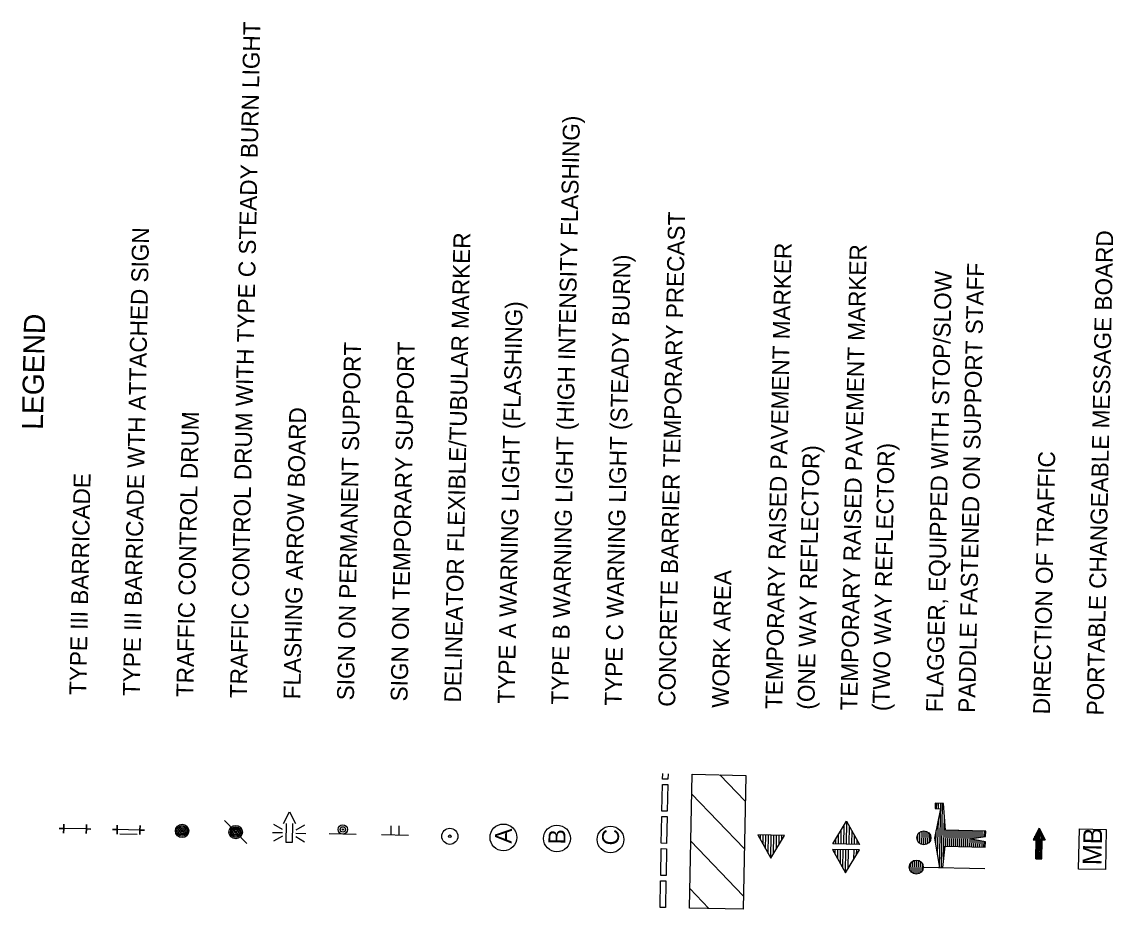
# Model space of a CAD drawing. Extents: x 327762 to 372975, y 127949 to 220470.
# Drawn here: x 327762 to 339988, y 174328 to 184269 of the extents above; entities that cross this region are included whole.
import ezdxf

# ---------------------------------------------------------------- set-up
doc = ezdxf.new("R2010")
doc.units = 0
for name, color, linetype in [('GSOUTLINE', 7, 'Continuous'), ('Level 31', 7, 'Continuous'), ('P_RDWY_Text', 7, 'Continuous'), ('P_TC', 7, 'Continuous')]:
    doc.layers.add(name, color=color, linetype=linetype)

msp = doc.modelspace()

# ---------------------------------------------------------------- linework, layer by layer
at = {"layer": 'GSOUTLINE'}
msp.add_lwpolyline([(335002, 175845), (335001, 175785), (334941, 175786), (334942, 175846)], dxfattribs=at)
for points in [[(334933, 175426), (334939, 175726), (334999, 175725), (334993, 175425)], [(334926, 175066), (334932, 175366), (334992, 175365), (334986, 175065)], [(334919, 174706), (334925, 175006), (334985, 175005), (334979, 174705)], [(334912, 174347), (334918, 174646), (334978, 174645), (334972, 174345)]]:
    msp.add_lwpolyline(points, close=True, dxfattribs=at)
at = {"layer": 'P_RDWY_Text'}
for p, q in [((339160, 175236), (339091, 175106)), ((339148, 174891), (339154, 175225)), ((339160, 175236), (339226, 175103)), ((339161, 174891), (339168, 175221)), ((339091, 175106), (339226, 175103)), ((339098, 175106), (339098, 175119)), ((339111, 175106), (339112, 175145)), ((339121, 174891), (339125, 175105)), ((339125, 175106), (339126, 175172)), ((339134, 174891), (339140, 175198)), ((339175, 174890), (339181, 175195)), ((339188, 174890), (339192, 175104)), ((339192, 175104), (339194, 175169)), ((339206, 175104), (339207, 175142)), ((339219, 175104), (339220, 175116)), ((339121, 174891), (339188, 174890)), ((339154, 174891), (339154, 174891))]:
    msp.add_line(p, q, dxfattribs=at)
at = {"layer": 'P_TC'}
for p, q in [((335867, 175537), (335582, 175833)), ((335856, 175006), (335266, 175620)), ((338054, 175453), (337988, 175125)), ((337996, 175515), (337994, 175455)), ((337994, 175455), (338054, 175453)), ((338088, 175513), (337996, 175515)), ((338010, 175454), (338011, 175514)), ((338032, 175454), (338033, 175514)), ((338041, 174793), (338056, 175513)), ((338064, 174793), (338078, 175513)), ((338110, 175212), (338088, 175513)), ((330692, 175289), (330761, 175419)), ((330761, 175419), (330827, 175286)), ((338022, 174936), (338030, 175331)), ((338088, 174884), (338098, 175376)), ((328231, 175231), (328180, 175232)), ((328180, 175232), (328231, 175231)), ((328231, 175231), (328229, 175180)), ((328229, 175180), (328231, 175231)), ((328231, 175231), (328232, 175282)), ((328232, 175282), (328231, 175231)), ((328485, 175226), (328231, 175231)), ((328485, 175226), (328484, 175175)), ((328484, 175175), (328485, 175226)), ((328486, 175277), (328485, 175226)), ((328485, 175226), (328486, 175277)), ((328485, 175226), (328536, 175225)), ((328536, 175225), (328485, 175226)), ((328830, 175219), (328779, 175220)), ((328779, 175220), (328830, 175219)), ((328830, 175219), (328829, 175168)), ((328829, 175168), (328830, 175219)), ((328830, 175219), (328831, 175270)), ((328831, 175270), (328830, 175219)), ((329085, 175214), (328830, 175219)), ((329085, 175214), (329084, 175163)), ((329084, 175163), (329085, 175214)), ((329086, 175265), (329085, 175214)), ((329085, 175214), (329086, 175265)), ((329085, 175214), (329136, 175213)), ((329136, 175213), (329085, 175214)), ((330283, 175062), (330032, 175323)), ((330683, 175219), (330586, 175278)), ((330722, 175074), (330726, 175288)), ((330793, 175286), (330789, 175073)), ((330834, 175216), (330932, 175271)), ((331898, 175157), (331900, 175262)), ((331988, 175156), (331990, 175261)), ((336939, 175212), (336936, 175056)), ((336970, 175263), (336966, 175055)), ((337001, 175314), (336996, 175055)), ((337030, 175262), (337026, 175054)), ((337059, 175209), (337056, 175053)), ((337866, 175049), (337870, 175206)), ((338001, 175049), (338005, 175208)), ((338560, 175203), (338110, 175212)), ((338114, 175032), (338117, 175212)), ((338136, 175032), (338140, 175212)), ((338159, 175031), (338162, 175211)), ((338181, 175031), (338185, 175211)), ((338204, 175030), (338207, 175210)), ((338226, 175030), (338230, 175210)), ((338249, 175029), (338252, 175209)), ((338271, 175029), (338275, 175209)), ((338294, 175029), (338297, 175209)), ((338316, 175028), (338320, 175208)), ((338339, 175028), (338342, 175208)), ((338361, 175027), (338365, 175207)), ((338385, 175119), (338387, 175207)), ((338408, 175122), (338410, 175206)), ((338431, 175125), (338432, 175206)), ((338453, 175128), (338455, 175205)), ((338476, 175131), (338477, 175205)), ((338498, 175135), (338500, 175204)), ((338521, 175138), (338522, 175204)), ((338543, 175141), (338545, 175204)), ((338558, 175143), (338560, 175203)), ((329054, 175164), (328859, 175168)), ((330682, 175182), (330570, 175184)), ((330681, 175144), (330583, 175090)), ((330832, 175141), (330929, 175083)), ((330833, 175179), (330945, 175177)), ((331506, 175165), (331207, 175171)), ((332093, 175153), (331793, 175159)), ((335845, 174476), (335256, 175090)), ((336037, 175109), (336038, 175161)), ((336066, 175056), (336068, 175160)), ((336095, 175004), (336098, 175159)), ((336124, 174951), (336128, 175159)), ((336153, 174898), (336158, 175158)), ((336184, 174950), (336188, 175158)), ((336215, 175001), (336218, 175157)), ((336246, 175052), (336248, 175156)), ((336277, 175104), (336278, 175156)), ((336877, 175109), (336876, 175057)), ((336908, 175160), (336906, 175056)), ((337088, 175157), (337086, 175053)), ((337117, 175104), (337116, 175052)), ((337800, 175088), (337801, 175169)), ((337822, 175064), (337824, 175192)), ((337844, 175052), (337847, 175203)), ((337889, 175052), (337892, 175202)), ((337912, 175062), (337914, 175190)), ((337935, 175086), (337936, 175165)), ((337988, 175125), (338041, 174794)), ((338378, 175117), (338558, 175143)), ((338557, 175083), (338378, 175117)), ((338384, 175027), (338385, 175115)), ((338406, 175026), (338408, 175111)), ((338429, 175026), (338430, 175107)), ((338451, 175025), (338453, 175103)), ((338474, 175025), (338475, 175098)), ((338496, 175024), (338497, 175094)), ((338519, 175024), (338520, 175090)), ((338541, 175024), (338542, 175086)), ((338556, 175023), (338557, 175083)), ((330789, 175073), (330722, 175074)), ((336874, 174945), (336875, 174997)), ((336903, 174893), (336905, 174997)), ((336932, 174840), (336935, 174996)), ((336961, 174787), (336965, 174995)), ((336990, 174735), (336995, 174995)), ((337021, 174786), (337025, 174994)), ((337083, 174889), (337085, 174993)), ((337114, 174940), (337115, 174992)), ((338079, 174793), (338106, 175032)), ((338106, 175032), (338556, 175023)), ((337715, 174760), (337716, 174840)), ((337737, 174735), (337739, 174864)), ((337759, 174724), (337762, 174874)), ((337781, 174720), (337785, 174877)), ((337804, 174723), (337807, 174873)), ((337827, 174734), (337829, 174862)), ((337850, 174758), (337851, 174837)), ((337861, 174797), (338551, 174783)), ((335460, 174335), (335245, 174560))]:
    msp.add_line(p, q, dxfattribs=at)
for points in [[(335241, 174340), (335271, 175840), (335872, 175827), (335842, 174328)], [(337146, 175052), (336846, 175058), (337001, 175314)], [(339601, 174777), (339610, 175227), (339910, 175221), (339901, 174771)], [(336308, 175155), (336008, 175161), (336153, 174898)], [(337145, 174992), (336845, 174998), (336990, 174735)]]:
    msp.add_lwpolyline(points, close=True, dxfattribs=at)
for centre, radius in [((329558, 175204), 75), ((329558, 175204), 60), ((329558, 175204), 45), ((329558, 175204), 30), ((329558, 175204), 15), ((329558, 175204), 7.5), ((330158, 175192), 75), ((330158, 175192), 60), ((330158, 175192), 45), ((330158, 175192), 30), ((330158, 175192), 15), ((331358, 175221), 52.5), ((331358, 175221), 30), ((331358, 175221), 7.5), ((332557, 175144), 90), ((333157, 175132), 150), ((333757, 175120), 150), ((334357, 175108), 150), ((337868, 175127), 78.4), ((330158, 175192), 7.5), ((332557, 175144), 15), ((337783, 174799), 78.4)]:
    msp.add_circle(centre, radius, dxfattribs=at)

# ---------------------------------------------------------------- texts
at = {"layer": 'Level 31'}
for s, height, p in [('TRAFFIC CONTROL DRUM WITH TYPE C STEADY BURN LIGHT', 189, (330282, 176690)), ('TYPE B WARNING LIGHT (HIGH INTENSITY FLASHING)', 189, (333882, 176618)), ('CONCRETE BARRIER TEMPORARY PRECAST', 189, (335081, 176594)), ('TYPE III BARRICADE WTH ATTACHED SIGN', 189, (329083, 176714)), ('DELINEATOR FLEXIBLE/TUBULAR MARKER', 189, (332682, 176642)), ('PORTABLE CHANGEABLE MESSAGE BOARD', 189, (339880, 176497)), ('TEMPORARY RAISED PAVEMENT MARKER', 189, (336281, 176569)), ('TEMPORARY RAISED PAVEMENT MARKER', 189, (337121, 176552)), ('TYPE C WARNING LIGHT (STEADY BURN)', 189, (334481, 176606)), ('FLAGGER, EQUIPPED WITH STOP/SLOW', 189, (338081, 176533)), ('PADDLE FASTENED ON SUPPORT STAFF', 189, (338441, 176526)), ('TYPE A WARNING LIGHT (FLASHING)', 189, (333282, 176630)), ('LEGEND', 236.4, (327998, 179697)), ('SIGN ON PERMANENT SUPPORT', 189, (331482, 176666)), ('SIGN ON TEMPORARY SUPPORT', 189, (332082, 176654)), ('TRAFFIC CONTROL DRUM', 189, (329682, 176702)), ('FLASHING ARROW BOARD', 189, (330882, 176678)), ('(ONE WAY REFLECTOR)', 189, (336641, 176562)), ('(TWO WAY REFLECTOR)', 189, (337481, 176545)), ('DIRECTION OF TRAFFIC', 189, (339280, 176509)), ('TYPE III BARRICADE', 189, (328483, 176726)), ('WORK AREA', 189, (335681, 176581))]:
    msp.add_text(s, height=height, rotation=88.8462, dxfattribs=at).set_placement(p)
at = {"layer": 'P_TC'}
for s, height, p in [('A', 189, (333250, 175062)), ('B', 189, (333850, 175053)), ('C', 189, (334450, 175041)), ('MB', 210, (339857, 174819))]:
    msp.add_text(s, height=height, rotation=88.8462, dxfattribs=at).set_placement(p)

doc.saveas('drawing.dxf')
